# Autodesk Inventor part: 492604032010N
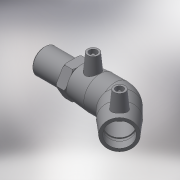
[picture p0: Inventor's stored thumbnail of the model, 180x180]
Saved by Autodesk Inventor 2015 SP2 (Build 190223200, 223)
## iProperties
Created: 2017-06
Part Number: 492604032010N
Material: Generic
Description: PLASSON 45° ELBOW TRANSITION MALE 32 x 1"
Document SubType Name: Modeling
Designer: KIM
Mass: 127.586 g
Surface Area: 385.407 cm^2
Volume: 127.586 cm^3
Density: 1 g/cm^3
Appearance: Default
Author: KIM
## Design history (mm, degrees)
derived "492604.ipt"
feature "Solid1::492604.ipt"
tag "TaggingFeature1"
body "Solid1"
other parameters: "d2" = 44, "d4" = 25.25, "d5" = 39.6, "d8" = 168 deg, "d10" = 17.6, "d11" = 5.86667, "d29" = 42, "d30" = 15, "d31" = 35.35, "d34" = 5 deg, "d41" = 4, "d42" = 14, "d43" = 0, "d49" = 32, "d50" = 20.8, "d51" = 17.6, "d52" = 45.32, "d54" = 135 deg, "d86" = 19.8, "d87" = 135 deg, "d88" = 101, "d90" = 44, "d91" = 0, "d92" = 44, "d93" = 0, "d101" = 3, "d102" = 0, "d107" = 0.1, "d108" = 22, "d109" = 33.249, "d111" = 12.5, "d112" = 44, "d113" = 23.2743, "d114" = 45, "d116" = 1.32, "d122" = 0, "d123" = 1.66245, "d_" = 32, "L_" = 151, "L_1" = 44, "D_" = 22, "A_" = 42, "d_2" = 12, "R_" = 33.249, "D_1" = 44
